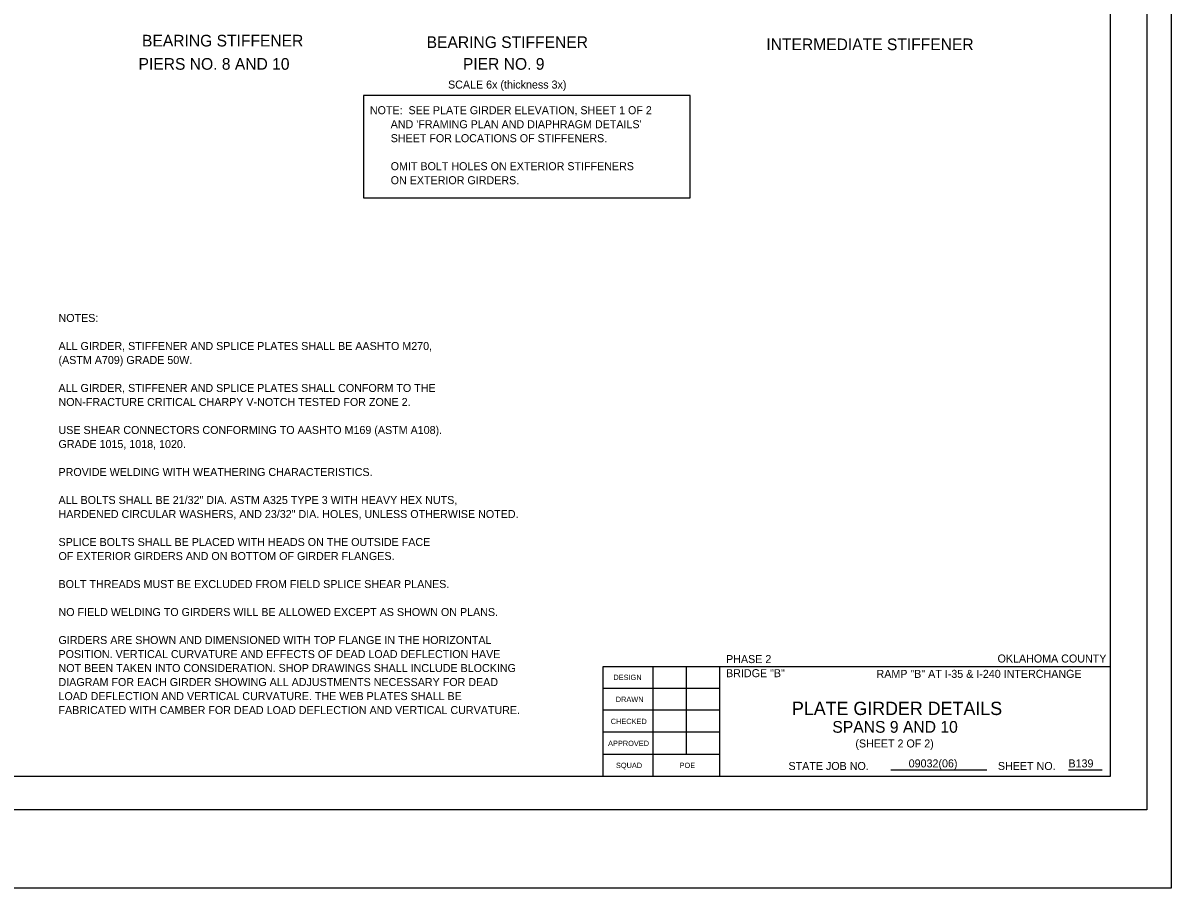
# Model space of a CAD drawing. Extents: x 4944 to 17449, y 3824 to 49087.
# Drawn here: x 14149 to 15801, y 32310 to 33555 of the extents above; entities that cross this region are included whole.
import ezdxf

# ---------------------------------------------------------------- set-up
doc = ezdxf.new("R2010")
doc.units = 0
for name, color, linetype in [('37_S_TXT', 7, 'Continuous'), ('3A', 7, 'Continuous'), ('BEAM', 7, 'Continuous'), ('DIM', 7, 'Continuous'), ('ID', 7, 'Continuous'), ('Level 14', 7, 'Continuous'), ('Level 17', 7, 'Continuous'), ('REVISED', 7, 'Continuous')]:
    doc.layers.add(name, color=color, linetype=linetype)

msp = doc.modelspace()

# ---------------------------------------------------------------- linework, layer by layer
at = {"layer": '37_S_TXT'}
msp.add_lwpolyline([(12345.1, 34613.8), (15801.2, 34613.8), (15801.2, 32309.8), (12345.1, 32309.8)], close=True, dxfattribs=at)
at = {"layer": '3A'}
msp.add_lwpolyline([(14638.8, 33303.4), (15109.3, 33303.4), (15109.3, 33451), (14638.8, 33451)], close=True, dxfattribs=at)
at = {"layer": 'DIM'}
msp.add_lwpolyline([(12502.3, 34534.6), (15766.4, 34534.6), (15766.4, 32422.6), (12502.3, 32422.6)], close=True, dxfattribs=at)
at = {"layer": 'Level 14'}
for p, q in [((14984, 32470.6), (14984, 32629)), ((14984, 32629), (15713.6, 32629)), ((15151.9, 32470.6), (15151.9, 32629.1)), ((15151.9, 32470.6), (15151.9, 32629.1))]:
    msp.add_line(p, q, dxfattribs=at)
msp.add_lwpolyline([(15713.6, 32470.6), (12689.5, 32470.6), (12689.5, 34486.6), (15713.6, 34486.6)], close=True, dxfattribs=at)
at = {"layer": 'Level 17'}
for p, q in [((15055.9, 32470.6), (15055.9, 32629.1)), ((15103.9, 32502.3), (15103.9, 32629.1)), ((15397.8, 32479.8), (15536.1, 32479.8)), ((15397.8, 32479.8), (15536.1, 32479.8)), ((15653.6, 32479.8), (15701.8, 32479.8)), ((15653.6, 32479.8), (15701.8, 32479.8))]:
    msp.add_line(p, q, dxfattribs=at)
for points in [[(15151.9, 32597.3), (14984, 32597.3)], [(15151.9, 32565.7), (14984, 32565.7)], [(15151.9, 32534), (14984, 32534)], [(15151.9, 32502.3), (14984, 32502.3)]]:
    msp.add_lwpolyline(points, dxfattribs=at)

# ---------------------------------------------------------------- texts
at = {"layer": '3A'}
for s, height, p in [('NOTE:  SEE PLATE GIRDER ELEVATION, SHEET 1 OF 2 ', 11.52, (14648.2, 33423.9)), ("       AND 'FRAMING PLAN AND DIAPHRAGM DETAILS' ", 11.52, (14648.2, 33403.7)), ('       SHEET FOR LOCATIONS OF STIFFENERS. ', 11.52, (14648.2, 33383.6)), ('       OMIT BOLT HOLES ON EXTERIOR STIFFENERS ', 11.52, (14648.2, 33343.3)), ('       ON EXTERIOR GIRDERS.', 11.52, (14648.2, 33323.1)), ('NOTES:', 11.52, (14200.1, 33124.8)), ('ALL GIRDER, STIFFENER AND SPLICE PLATES SHALL BE AASHTO M270,', 11.52, (14200.1, 33084.4)), ('(ASTM A709) GRADE 50W.', 11.52, (14200.1, 33064.3)), ('ALL GIRDER, STIFFENER AND SPLICE PLATES SHALL CONFORM TO THE', 11.52, (14200.1, 33024)), ('NON-FRACTURE CRITICAL CHARPY V-NOTCH TESTED FOR ZONE 2.', 11.52, (14200.1, 33003.8)), ('USE SHEAR CONNECTORS CONFORMING TO AASHTO M169 (ASTM A108).', 11.52, (14200.1, 32963.5)), ('GRADE 1015, 1018, 1020.', 11.52, (14200.1, 32943.3)), ('PROVIDE WELDING WITH WEATHERING CHARACTERISTICS.  ', 11.52, (14200.1, 32903)), ('ALL BOLTS SHALL BE 21/32" DIA. ASTM A325 TYPE 3 WITH HEAVY HEX NUTS, ', 11.52, (14200.1, 32862.7)), ('HARDENED CIRCULAR WASHERS, AND 23/32" DIA. HOLES, UNLESS OTHERWISE NOTED.  ', 11.52, (14200.1, 32842.5)), ('SPLICE BOLTS SHALL BE PLACED WITH HEADS ON THE OUTSIDE FACE', 11.52, (14200.1, 32802.2)), ('OF EXTERIOR GIRDERS AND ON BOTTOM OF GIRDER FLANGES.  ', 11.52, (14200.1, 32782)), ('BOLT THREADS MUST BE EXCLUDED FROM FIELD SPLICE SHEAR PLANES.', 11.52, (14200.1, 32741.7)), ('NO FIELD WELDING TO GIRDERS WILL BE ALLOWED EXCEPT AS SHOWN ON PLANS.', 11.52, (14200.1, 32701.4)), ('GIRDERS ARE SHOWN AND DIMENSIONED WITH TOP FLANGE IN THE HORIZONTAL', 11.52, (14200.1, 32661.1)), ('POSITION. VERTICAL CURVATURE AND EFFECTS OF DEAD LOAD DEFLECTION HAVE ', 11.52, (14200.1, 32640.9)), ('NOT BEEN TAKEN INTO CONSIDERATION. SHOP DRAWINGS SHALL INCLUDE BLOCKING ', 11.52, (14200.1, 32620.8)), ('PHASE 2', 11.52, (15160.8, 32633.7)), ('OKLAHOMA COUNTY', 11.52, (15551.5, 32634.5)), ('BRIDGE "B"', 11.52, (15160.8, 32613.4)), ('RAMP "B" AT I-35 & I-240 INTERCHANGE', 11.52, (15377.3, 32612.4)), ('DIAGRAM FOR EACH GIRDER SHOWING ALL ADJUSTMENTS NECESSARY FOR DEAD ', 11.52, (14200.1, 32600.6)), ('LOAD DEFLECTION AND VERTICAL CURVATURE. THE WEB PLATES SHALL BE ', 11.52, (14200.1, 32580.4)), ('FABRICATED WITH CAMBER FOR DEAD LOAD DEFLECTION AND VERTICAL CURVATURE.', 11.52, (14200.1, 32560.3)), ('(SHEET 2 OF 2)', 11.5, (15346.9, 32512.2)), ('09032(06)', 11.52, (15423.6, 32483.5)), ('B139', 11.52, (15653.5, 32483.5))]:
    msp.add_text(s, height=height, dxfattribs=at).set_placement(p)
at = {"layer": 'BEAM'}
for s, height, p in [('BEARING STIFFENER', 16.8, (14320.3, 33521.4)), ('BEARING STIFFENER', 16.8, (14729.9, 33519.2)), ('INTERMEDIATE STIFFENER', 16.8, (15218.8, 33516.1)), ('PIERS NO. 8 AND 10', 16.8, (14315.3, 33487.9)), ('PIER NO. 9', 16.8, (14782.1, 33487.9)), ('PLATE GIRDER DETAILS', 19.2, (15255.6, 32558.9))]:
    msp.add_text(s, height=height, dxfattribs=at).set_placement(p)
at = {"layer": 'DEFPOINTS'}
msp.add_text('SCALE 6x (thickness 3x)', height=11.52, dxfattribs=at).set_placement((14760.7, 33460.8))
at = {"layer": 'ID'}
msp.add_text('SPANS 9 AND 10', height=16.875, dxfattribs=at).set_placement((15313.7, 32533.4))
at = {"layer": 'REVISED'}
for s, height, p in [('DESIGN', 7.68, (14998.6, 32609.3)), ('DRAWN', 7.68, (15002, 32577.6)), ('CHECKED', 7.68, (14994.8, 32545.9)), ('APPROVED', 7.68, (14991, 32514.3)), ('SQUAD', 7.68, (15002.3, 32482.6)), ('POE', 7.68, (15093.9, 32482.6)), ('STATE JOB NO.', 11.52, (15250.6, 32479.8)), ('STATE JOB NO.', 11.52, (15250.6, 32479.8)), ('SHEET NO. ', 11.52, (15552, 32479.8)), ('SHEET NO. ', 11.52, (15552, 32479.8))]:
    msp.add_text(s, height=height, dxfattribs=at).set_placement(p)

doc.saveas('drawing.dxf')
